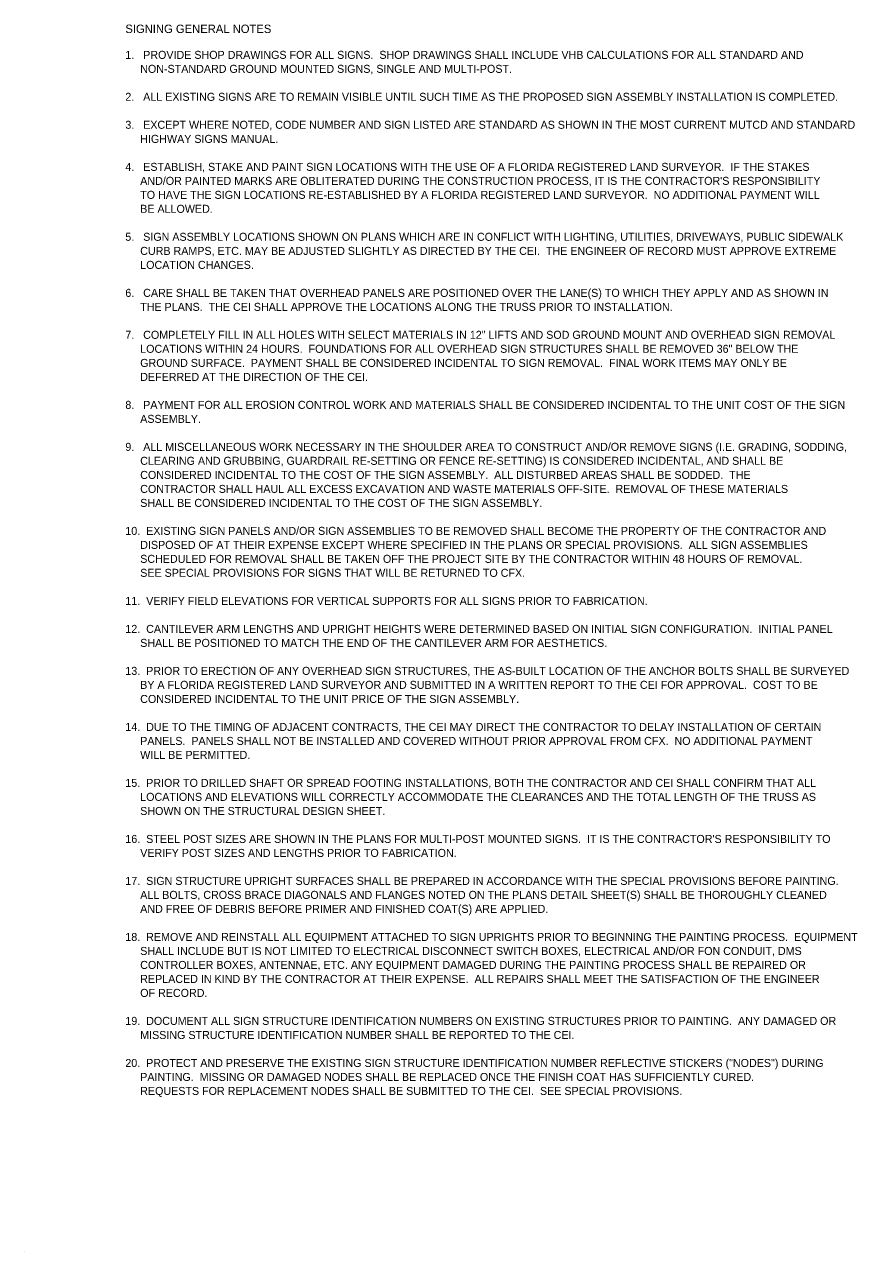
# Model space of a CAD drawing. Extents: x 2479946 to 2481502, y 3680184 to 3681234.
# Drawn here: x 2479946 to 2480648, y 3680184 to 3681219 of the extents above; entities that cross this region are included whole.
import ezdxf

# ---------------------------------------------------------------- set-up
doc = ezdxf.new("R2010")
doc.units = 0
doc.layers.add('AdhocPoint_dp', color=7, linetype='Continuous')
doc.layers.add('TextLabel', color=7, linetype='Continuous')

msp = doc.modelspace()

# ---------------------------------------------------------------- linework, layer by layer
at = {"layer": 'AdhocPoint_dp'}
msp.add_line((2479945.9, 3680184.2), (2479945.9, 3680184.2), dxfattribs=at)

# ---------------------------------------------------------------- texts
at = {"layer": 'TextLabel'}
for s, height, p in [('SIGNING GENERAL NOTES', 7.08, (2480030.9, 3681212.2)), ('1.   PROVIDE SHOP DRAWINGS FOR ALL SIGNS.  SHOP DRAWINGS SHALL INCLUDE VHB CALCULATIONS FOR ALL STANDARD AND', 6.75, (2480030.9, 3681190.4)), ('     NON-STANDARD GROUND MOUNTED SIGNS, SINGLE AND MULTI-POST.', 6.75, (2480030.9, 3681178.6)), ('2.   ALL EXISTING SIGNS ARE TO REMAIN VISIBLE UNTIL SUCH TIME AS THE PROPOSED SIGN ASSEMBLY INSTALLATION IS COMPLETED.', 6.75, (2480030.9, 3681155)), ('3.   EXCEPT WHERE NOTED, CODE NUMBER AND SIGN LISTED ARE STANDARD AS SHOWN IN THE MOST CURRENT MUTCD AND STANDARD ', 6.75, (2480030.9, 3681131.4)), ('     HIGHWAY SIGNS MANUAL.', 6.75, (2480030.9, 3681119.5)), ('4.   ESTABLISH, STAKE AND PAINT SIGN LOCATIONS WITH THE USE OF A FLORIDA REGISTERED LAND SURVEYOR.  IF THE STAKES', 6.75, (2480030.9, 3681095.9)), ("     AND/OR PAINTED MARKS ARE OBLITERATED DURING THE CONSTRUCTION PROCESS, IT IS THE CONTRACTOR'S RESPONSIBILITY", 6.75, (2480030.9, 3681084.1)), ('     TO HAVE THE SIGN LOCATIONS RE-ESTABLISHED BY A FLORIDA REGISTERED LAND SURVEYOR.  NO ADDITIONAL PAYMENT WILL', 6.75, (2480030.9, 3681072.3)), ('     BE ALLOWED.', 6.75, (2480030.9, 3681060.5)), ('5.   SIGN ASSEMBLY LOCATIONS SHOWN ON PLANS WHICH ARE IN CONFLICT WITH LIGHTING, UTILITIES, DRIVEWAYS, PUBLIC SIDEWALK', 6.75, (2480030.9, 3681036.9)), ('     CURB RAMPS, ETC. MAY BE ADJUSTED SLIGHTLY AS DIRECTED BY THE CEI.  THE ENGINEER OF RECORD MUST APPROVE EXTREME', 6.75, (2480030.9, 3681025)), ('     LOCATION CHANGES. ', 6.75, (2480030.9, 3681013.2)), ('6.   CARE SHALL BE TAKEN THAT OVERHEAD PANELS ARE POSITIONED OVER THE LANE(S) TO WHICH THEY APPLY AND AS SHOWN IN', 6.75, (2480030.9, 3680989.6)), ('     THE PLANS.  THE CEI SHALL APPROVE THE LOCATIONS ALONG THE TRUSS PRIOR TO INSTALLATION.', 6.75, (2480030.9, 3680977.8)), ('7.   COMPLETELY FILL IN ALL HOLES WITH SELECT MATERIALS IN 12" LIFTS AND SOD GROUND MOUNT AND OVERHEAD SIGN REMOVAL', 6.75, (2480030.9, 3680954.2)), ('     LOCATIONS WITHIN 24 HOURS.  FOUNDATIONS FOR ALL OVERHEAD SIGN STRUCTURES SHALL BE REMOVED 36" BELOW THE', 6.75, (2480030.9, 3680942.4)), ('     GROUND SURFACE.  PAYMENT SHALL BE CONSIDERED INCIDENTAL TO SIGN REMOVAL.  FINAL WORK ITEMS MAY ONLY BE', 6.75, (2480030.9, 3680930.5)), ('     DEFERRED AT THE DIRECTION OF THE CEI.', 6.75, (2480030.9, 3680918.7)), ('8.   PAYMENT FOR ALL EROSION CONTROL WORK AND MATERIALS SHALL BE CONSIDERED INCIDENTAL TO THE UNIT COST OF THE SIGN', 6.75, (2480030.9, 3680895.1)), ('     ASSEMBLY.', 6.75, (2480030.9, 3680883.3)), ('9.   ALL MISCELLANEOUS WORK NECESSARY IN THE SHOULDER AREA TO CONSTRUCT AND/OR REMOVE SIGNS (I.E. GRADING, SODDING,', 6.75, (2480030.9, 3680859.7)), ('     CLEARING AND GRUBBING, GUARDRAIL RE-SETTING OR FENCE RE-SETTING) IS CONSIDERED INCIDENTAL, AND SHALL BE', 6.75, (2480030.9, 3680847.9)), ('     CONSIDERED INCIDENTAL TO THE COST OF THE SIGN ASSEMBLY.  ALL DISTURBED AREAS SHALL BE SODDED.  THE  ', 6.75, (2480030.9, 3680836)), ('     CONTRACTOR SHALL HAUL ALL EXCESS EXCAVATION AND WASTE MATERIALS OFF-SITE.  REMOVAL OF THESE MATERIALS  ', 6.75, (2480030.9, 3680824.2)), ('     SHALL BE CONSIDERED INCIDENTAL TO THE COST OF THE SIGN ASSEMBLY.', 6.75, (2480030.9, 3680812.4)), ('10.  EXISTING SIGN PANELS AND/OR SIGN ASSEMBLIES TO BE REMOVED SHALL BECOME THE PROPERTY OF THE CONTRACTOR AND', 6.75, (2480030.9, 3680788.8)), ('     DISPOSED OF AT THEIR EXPENSE EXCEPT WHERE SPECIFIED IN THE PLANS OR SPECIAL PROVISIONS.  ALL SIGN ASSEMBLIES', 6.75, (2480030.9, 3680777)), ('     SCHEDULED FOR REMOVAL SHALL BE TAKEN OFF THE PROJECT SITE BY THE CONTRACTOR WITHIN 48 HOURS OF REMOVAL.', 6.75, (2480030.9, 3680765.2)), ('     SEE SPECIAL PROVISIONS FOR SIGNS THAT WILL BE RETURNED TO CFX.', 6.75, (2480030.9, 3680753.4)), ('11.  VERIFY FIELD ELEVATIONS FOR VERTICAL SUPPORTS FOR ALL SIGNS PRIOR TO FABRICATION.', 6.75, (2480030.9, 3680729.7)), ('12.  CANTILEVER ARM LENGTHS AND UPRIGHT HEIGHTS WERE DETERMINED BASED ON INITIAL SIGN CONFIGURATION.  INITIAL PANEL', 6.75, (2480030.9, 3680706.1)), ('     SHALL BE POSITIONED TO MATCH THE END OF THE CANTILEVER ARM FOR AESTHETICS.', 6.75, (2480030.9, 3680694.3)), ('13.  PRIOR TO ERECTION OF ANY OVERHEAD SIGN STRUCTURES, THE AS-BUILT LOCATION OF THE ANCHOR BOLTS SHALL BE SURVEYED', 6.75, (2480030.9, 3680670.7)), ('     BY A FLORIDA REGISTERED LAND SURVEYOR AND SUBMITTED IN A WRITTEN REPORT TO THE CEI FOR APPROVAL.  COST TO BE', 6.75, (2480030.9, 3680658.9)), ('     CONSIDERED INCIDENTAL TO THE UNIT PRICE OF THE SIGN ASSEMBLY.', 6.75, (2480030.9, 3680647)), ('14.  DUE TO THE TIMING OF ADJACENT CONTRACTS, THE CEI MAY DIRECT THE CONTRACTOR TO DELAY INSTALLATION OF CERTAIN', 6.75, (2480030.9, 3680623.4)), ('     PANELS.  PANELS SHALL NOT BE INSTALLED AND COVERED WITHOUT PRIOR APPROVAL FROM CFX.  NO ADDITIONAL PAYMENT', 6.75, (2480030.9, 3680611.6)), ('     WILL BE PERMITTED.', 6.75, (2480030.9, 3680599.8)), ('15.  PRIOR TO DRILLED SHAFT OR SPREAD FOOTING INSTALLATIONS, BOTH THE CONTRACTOR AND CEI SHALL CONFIRM THAT ALL', 6.75, (2480030.9, 3680576.2)), ('     LOCATIONS AND ELEVATIONS WILL CORRECTLY ACCOMMODATE THE CLEARANCES AND THE TOTAL LENGTH OF THE TRUSS AS', 6.75, (2480030.9, 3680564.4)), ('     SHOWN ON THE STRUCTURAL DESIGN SHEET.', 6.75, (2480030.9, 3680552.5)), ("16.  STEEL POST SIZES ARE SHOWN IN THE PLANS FOR MULTI-POST MOUNTED SIGNS.  IT IS THE CONTRACTOR'S RESPONSIBILITY TO", 6.75, (2480030.9, 3680528.9)), ('     VERIFY POST SIZES AND LENGTHS PRIOR TO FABRICATION.', 6.75, (2480030.9, 3680517.1)), ('17.  SIGN STRUCTURE UPRIGHT SURFACES SHALL BE PREPARED IN ACCORDANCE WITH THE SPECIAL PROVISIONS BEFORE PAINTING.', 6.75, (2480030.9, 3680493.5)), ('     ALL BOLTS, CROSS BRACE DIAGONALS AND FLANGES NOTED ON THE PLANS DETAIL SHEET(S) SHALL BE THOROUGHLY CLEANED', 6.75, (2480030.9, 3680481.7)), ('     AND FREE OF DEBRIS BEFORE PRIMER AND FINISHED COAT(S) ARE APPLIED.', 6.75, (2480030.9, 3680469.9)), ('18.  REMOVE AND REINSTALL ALL EQUIPMENT ATTACHED TO SIGN UPRIGHTS PRIOR TO BEGINNING THE PAINTING PROCESS.  EQUIPMENT', 6.75, (2480030.9, 3680446.2)), ('     SHALL INCLUDE BUT IS NOT LIMITED TO ELECTRICAL DISCONNECT SWITCH BOXES, ELECTRICAL AND/OR FON CONDUIT, DMS', 6.75, (2480030.9, 3680434.4)), ('     CONTROLLER BOXES, ANTENNAE, ETC. ANY EQUIPMENT DAMAGED DURING THE PAINTING PROCESS SHALL BE REPAIRED OR', 6.75, (2480030.9, 3680422.6)), ('     REPLACED IN KIND BY THE CONTRACTOR AT THEIR EXPENSE.  ALL REPAIRS SHALL MEET THE SATISFACTION OF THE ENGINEER', 6.75, (2480030.9, 3680410.8)), ('     OF RECORD.', 6.75, (2480030.9, 3680399)), ('19.  DOCUMENT ALL SIGN STRUCTURE IDENTIFICATION NUMBERS ON EXISTING STRUCTURES PRIOR TO PAINTING.  ANY DAMAGED OR', 6.75, (2480030.9, 3680375.4)), ('     MISSING STRUCTURE IDENTIFICATION NUMBER SHALL BE REPORTED TO THE CEI.', 6.75, (2480030.9, 3680363.5)), ('20.  PROTECT AND PRESERVE THE EXISTING SIGN STRUCTURE IDENTIFICATION NUMBER REFLECTIVE STICKERS ("NODES") DURING', 6.75, (2480030.9, 3680339.9)), ('     PAINTING.  MISSING OR DAMAGED NODES SHALL BE REPLACED ONCE THE FINISH COAT HAS SUFFICIENTLY CURED.', 6.75, (2480030.9, 3680328.1)), ('     REQUESTS FOR REPLACEMENT NODES SHALL BE SUBMITTED TO THE CEI.  SEE SPECIAL PROVISIONS.', 6.75, (2480030.9, 3680316.3))]:
    msp.add_text(s, height=height, dxfattribs=at).set_placement(p)

doc.saveas('drawing.dxf')
